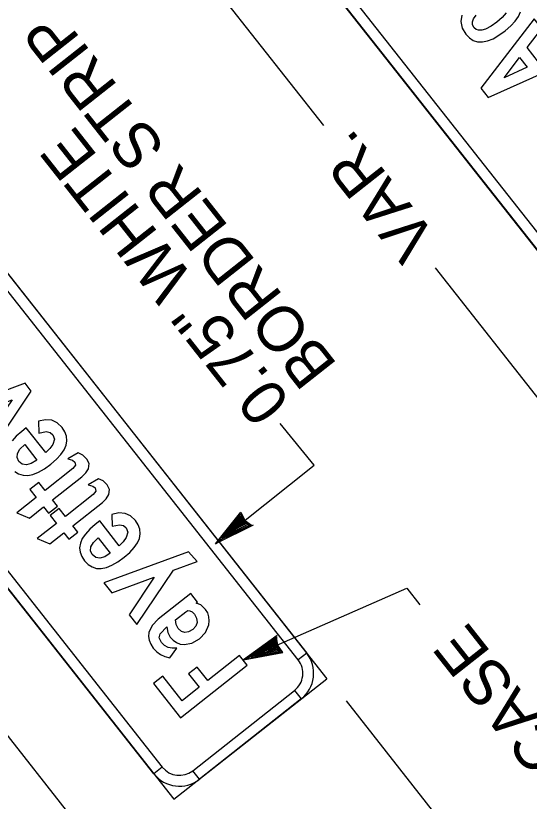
# Model space of a CAD drawing. Extents: x 672438 to 673763, y 1673171 to 1675010.
# Drawn here: x 673330.7 to 673378.2, y 1674719.6 to 1674792.2 of the extents above; entities that cross this region are included whole.
import ezdxf

# ---------------------------------------------------------------- set-up
doc = ezdxf.new("R2010")
doc.units = 0
for name, color, linetype in [('C-ANNO-SYMB', 7, 'Continuous'), ('Level 1', 7, 'Continuous'), ('V-SIGNAL-LOOP', 7, 'Continuous')]:
    doc.layers.add(name, color=color, linetype=linetype)

msp = doc.modelspace()

# ---------------------------------------------------------------- linework, layer by layer
at = {"layer": 'C-ANNO-SYMB'}
for p, q in [((673346.166, 1674812.112), (673390.741, 1674755.57)), ((673318.61, 1674782.748), (673359.471, 1674730.917)), ((673304.474, 1674771.604), (673345.335, 1674719.774)), ((673357.613, 1674733.273), (673356.828, 1674732.654)), ((673345.335, 1674719.774), (673359.471, 1674730.917)), ((673356.496, 1674729.845), (673357.115, 1674729.06)), ((673344.263, 1674722.749), (673343.478, 1674722.13)), ((673347.691, 1674721.631), (673347.072, 1674722.416))]:
    msp.add_line(p, q, dxfattribs=at)
for points in [[(673348.809, 1674810.375), (673389.669, 1674758.545), (673388.884, 1674757.926), (673348.023, 1674809.756), (673348.809, 1674810.375), (673348.809, 1674810.375)], [(673356.828, 1674732.654), (673319.682, 1674779.773), (673320.467, 1674780.392), (673357.613, 1674733.273), (673356.828, 1674732.654), (673356.828, 1674732.654)], [(673307.117, 1674769.867), (673344.263, 1674722.749), (673343.478, 1674722.13), (673306.332, 1674769.248), (673307.117, 1674769.867), (673307.117, 1674769.867)], [(673328.706, 1674752.423), (673332.141, 1674757.508), (673331.568, 1674758.235), (673325.816, 1674756.089), (673326.6, 1674755.207), (673330.366, 1674756.681), (673328.07, 1674753.342)], [(673335.529, 1674751.241), (673335.946, 1674751.111), (673336.182, 1674750.939), (673336.249, 1674750.652), (673336.003, 1674750.345), (673333.42, 1674748.308), (673332.841, 1674749.042), (673332.021, 1674748.396), (673332.6, 1674747.662), (673330.821, 1674746.26), (673331.984, 1674745.765), (673333.286, 1674746.792), (673333.745, 1674746.209), (673334.565, 1674746.855), (673334.106, 1674747.438), (673336.837, 1674749.591), (673337.204, 1674749.948), (673337.43, 1674750.331), (673337.486, 1674750.798), (673337.288, 1674751.227), (673336.908, 1674751.597), (673336.487, 1674751.786)], [(673337.412, 1674748.854), (673337.828, 1674748.723), (673338.064, 1674748.551), (673338.131, 1674748.265), (673337.885, 1674747.958), (673335.302, 1674745.921), (673334.723, 1674746.655), (673333.903, 1674746.009), (673334.482, 1674745.275), (673332.703, 1674743.873), (673333.866, 1674743.378), (673335.168, 1674744.404), (673335.628, 1674743.821), (673336.447, 1674744.468), (673335.988, 1674745.051), (673338.719, 1674747.204), (673339.087, 1674747.561), (673339.312, 1674747.943), (673339.368, 1674748.41), (673339.17, 1674748.839), (673338.79, 1674749.21), (673338.37, 1674749.399)], [(673347.499, 1674741.755), (673346.698, 1674742.646), (673338.865, 1674739.786), (673339.605, 1674738.847), (673343.521, 1674740.312), (673341.198, 1674736.827), (673341.903, 1674735.933), (673345.309, 1674740.944)], [(673352.117, 1674732.169), (673351.402, 1674733.077), (673348.468, 1674730.764), (673347.494, 1674732), (673346.682, 1674731.361), (673347.657, 1674730.124), (673346.086, 1674728.886), (673344.304, 1674731.147), (673343.458, 1674730.48), (673345.956, 1674727.311)], [(673347.072, 1674722.416), (673356.496, 1674729.845), (673357.115, 1674729.06), (673347.691, 1674721.631), (673347.072, 1674722.416), (673347.072, 1674722.416)]]:
    msp.add_lwpolyline(points, close=True, dxfattribs=at)
for points in [[(673371.959, 1674792.26), (673371.866, 1674791.664), (673371.991, 1674791.061), (673372.324, 1674790.488), (673372.655, 1674790.145), (673373.02, 1674789.916), (673373.422, 1674789.793), (673373.859, 1674789.779), (673374.335, 1674789.874), (673374.844, 1674790.076), (673375.39, 1674790.387), (673375.973, 1674790.806), (673376.495, 1674791.258), (673376.905, 1674791.701), (673377.207, 1674792.137), (673377.393, 1674792.565)], [(673376.067, 1674792.472), (673375.704, 1674792.032), (673375.208, 1674791.593), (673374.668, 1674791.219), (673374.148, 1674790.969), (673373.807, 1674790.867), (673373.514, 1674790.854), (673373.276, 1674790.927), (673373.086, 1674791.089), (673372.954, 1674791.346), (673372.941, 1674791.623), (673373.05, 1674791.924), (673373.274, 1674792.244)], [(673381.774, 1674787.943), (673381.069, 1674788.837), (673379.044, 1674787.917), (673377.996, 1674789.246), (673379.348, 1674791.02), (673378.638, 1674791.92), (673373.702, 1674785.509), (673374.388, 1674784.639), (673381.774, 1674787.943)], [(673377.996, 1674787.443), (673375.864, 1674786.468), (673377.29, 1674788.338), (673377.996, 1674787.443)], [(673330.613, 1674750.087), (673330.98, 1674749.853), (673331.385, 1674749.728), (673331.823, 1674749.715), (673332.303, 1674749.81), (673332.815, 1674750.014), (673333.363, 1674750.328), (673333.949, 1674750.75), (673334.468, 1674751.198), (673334.876, 1674751.64), (673335.174, 1674752.074), (673335.358, 1674752.5), (673335.436, 1674752.919), (673335.398, 1674753.334), (673335.251, 1674753.741), (673334.992, 1674754.14), (673334.547, 1674754.568), (673334.036, 1674754.806), (673333.46, 1674754.854), (673332.814, 1674754.71), (673332.851, 1674753.63), (673333.525, 1674753.758), (673333.881, 1674753.686), (673334.147, 1674753.473), (673334.284, 1674753.071), (673334.127, 1674752.57), (673333.861, 1674752.186), (673333.493, 1674751.819)], [(673333.493, 1674751.819), (673331.689, 1674754.106), (673331.264, 1674753.771), (673330.764, 1674753.335), (673330.367, 1674752.902)], [(673332.666, 1674751.127), (673332.149, 1674750.805), (673331.699, 1674750.677), (673331.318, 1674750.741), (673331.005, 1674750.997), (673330.837, 1674751.351), (673330.868, 1674751.731), (673331.104, 1674752.131), (673331.54, 1674752.556), (673332.666, 1674751.127)], [(673340.278, 1674743.212), (673338.474, 1674745.499), (673338.05, 1674745.164), (673337.549, 1674744.728), (673337.152, 1674744.295), (673336.867, 1674743.869), (673336.687, 1674743.449), (673336.621, 1674743.032), (673336.66, 1674742.621), (673336.811, 1674742.217), (673337.065, 1674741.82), (673337.398, 1674741.48), (673337.765, 1674741.246), (673338.17, 1674741.121), (673338.608, 1674741.108), (673339.088, 1674741.203), (673339.6, 1674741.407), (673340.149, 1674741.721), (673340.735, 1674742.143), (673341.253, 1674742.591), (673341.661, 1674743.033), (673341.96, 1674743.467), (673342.143, 1674743.893), (673342.221, 1674744.312), (673342.184, 1674744.727), (673342.037, 1674745.134), (673341.777, 1674745.533), (673341.332, 1674745.961), (673340.821, 1674746.199), (673340.245, 1674746.247), (673339.599, 1674746.103), (673339.636, 1674745.022), (673340.31, 1674745.151), (673340.666, 1674745.079), (673340.932, 1674744.866), (673341.069, 1674744.464), (673340.913, 1674743.963), (673340.646, 1674743.579), (673340.278, 1674743.212)], [(673339.451, 1674742.52), (673338.934, 1674742.198), (673338.484, 1674742.07), (673338.103, 1674742.134), (673337.791, 1674742.39), (673337.623, 1674742.744), (673337.654, 1674743.124), (673337.889, 1674743.524), (673338.325, 1674743.949), (673339.451, 1674742.52)], [(673347.531, 1674737.987), (673346.894, 1674738.795), (673343.894, 1674736.43), (673343.316, 1674735.836), (673343.019, 1674735.195), (673342.988, 1674734.831), (673343.043, 1674734.47), (673343.19, 1674734.108), (673343.425, 1674733.752), (673343.746, 1674733.411), (673344.106, 1674733.148), (673344.511, 1674732.961), (673344.953, 1674732.851), (673345.608, 1674733.729), (673345.179, 1674733.73), (673344.797, 1674733.818), (673344.474, 1674733.995), (673344.203, 1674734.256), (673343.985, 1674734.692), (673344.051, 1674735.078), (673344.667, 1674735.729), (673344.761, 1674735.185), (673344.976, 1674734.766), (673345.258, 1674734.471), (673345.566, 1674734.259), (673345.908, 1674734.125), (673346.277, 1674734.069), (673347.003, 1674734.192), (673347.709, 1674734.601), (673348.254, 1674735.187), (673348.552, 1674735.891), (673348.609, 1674736.281), (673348.576, 1674736.65), (673348.459, 1674736.995), (673348.254, 1674737.317), (673347.823, 1674737.739), (673347.407, 1674737.889), (673347.531, 1674737.987)], [(673345.477, 1674736.368), (673346.425, 1674737.115), (673346.619, 1674737.213), (673346.817, 1674737.207), (673347.022, 1674737.096), (673347.229, 1674736.879), (673347.44, 1674736.507), (673347.479, 1674736.131), (673347.357, 1674735.778), (673347.072, 1674735.47), (673346.694, 1674735.243), (673346.345, 1674735.179), (673346.025, 1674735.281), (673345.731, 1674735.549), (673345.537, 1674735.919), (673345.477, 1674736.368)]]:
    msp.add_lwpolyline(points, dxfattribs=at)
for centre, radius, start, end in [((673355.257, 1674731.416), 3, 308.25039, 38.2506), ((673355.257, 1674731.416), 2, 308.25039, 38.2506), ((673345.834, 1674723.987), 2, 218.25075, 308.25039), ((673345.834, 1674723.987), 3, 218.25075, 308.25039)]:
    msp.add_arc(centre, radius, start, end, dxfattribs=at)
at = {"layer": 'Level 1'}
for p, q in [((673359.186, 1674782.058), (673343.23, 1674802.298)), ((673384.125, 1674750.354), (673369.51, 1674768.893)), ((673349.19, 1674743.399), (673351.51, 1674746.31)), ((673351.51, 1674746.31), (673351.902, 1674745.55)), ((673349.408, 1674743.636), (673351.491, 1674746.161)), ((673349.759, 1674743.911), (673351.489, 1674745.993)), ((673349.977, 1674744.011), (673351.532, 1674745.727)), ((673350.049, 1674744.135), (673351.49, 1674745.861)), ((673350.483, 1674744.474), (673351.476, 1674745.583)), ((673351.535, 1674745.596), (673351.029, 1674744.837)), ((673351.476, 1674745.583), (673351.83, 1674745.261)), ((673351.489, 1674745.993), (673351.627, 1674745.733)), ((673351.49, 1674745.861), (673352.171, 1674745.163)), ((673351.491, 1674746.161), (673351.833, 1674745.596)), ((673351.532, 1674745.727), (673351.992, 1674745.222)), ((673351.911, 1674745.325), (673351.535, 1674745.596)), ((673351.627, 1674745.733), (673352.171, 1674745.163)), ((673351.833, 1674745.596), (673352.503, 1674745.123)), ((673352.65, 1674745.105), (673349.19, 1674743.399)), ((673352.293, 1674745.091), (673349.45, 1674743.667)), ((673352.458, 1674745.053), (673349.61, 1674743.759)), ((673352.171, 1674745.163), (673349.977, 1674744.011)), ((673352.171, 1674745.163), (673350.049, 1674744.135)), ((673351.992, 1674745.222), (673350.483, 1674744.474)), ((673350.87, 1674744.744), (673351.441, 1674745.456)), ((673351.83, 1674745.261), (673350.87, 1674744.744)), ((673351.205, 1674745.039), (673351.471, 1674745.379)), ((673351.722, 1674745.31), (673351.205, 1674745.039)), ((673351.441, 1674745.456), (673351.722, 1674745.31)), ((673351.471, 1674745.379), (673351.553, 1674745.314)), ((673351.553, 1674745.314), (673351.911, 1674745.325)), ((673351.902, 1674745.55), (673352.144, 1674745.241)), ((673352.144, 1674745.241), (673352.458, 1674745.053)), ((673352.503, 1674745.123), (673352.284, 1674745.186)), ((673352.284, 1674745.186), (673352.293, 1674745.091)), ((673351.029, 1674744.837), (673350.776, 1674744.737)), ((673354.877, 1674734.922), (673351.757, 1674732.653)), ((673354.741, 1674734.777), (673352.271, 1674732.857)), ((673354.761, 1674734.411), (673354.741, 1674734.777)), ((673354.825, 1674734.784), (673354.779, 1674734.56)), ((673354.931, 1674733.97), (673354.825, 1674734.784)), ((673354.698, 1674734.612), (673352.115, 1674732.758)), ((673354.705, 1674734.471), (673352.665, 1674733.065)), ((673354.705, 1674734.471), (673352.808, 1674733.071)), ((673354.674, 1674734.285), (673353.31, 1674733.297)), ((673354.633, 1674734.123), (673353.729, 1674733.514)), ((673354.627, 1674734.005), (673354.146, 1674733.674)), ((673354.551, 1674733.854), (673354.727, 1674734.165)), ((673354.625, 1674733.688), (673354.627, 1674734.005)), ((673354.754, 1674733.661), (673354.633, 1674734.123)), ((673354.907, 1674733.642), (673354.674, 1674734.285)), ((673354.779, 1674734.56), (673354.698, 1674734.612)), ((673354.956, 1674733.724), (673354.705, 1674734.471)), ((673355.006, 1674733.544), (673354.705, 1674734.471)), ((673354.727, 1674734.165), (673354.792, 1674733.706)), ((673354.923, 1674734.053), (673354.761, 1674734.411)), ((673355.412, 1674733.352), (673354.923, 1674734.053)), ((673355.272, 1674733.405), (673354.931, 1674733.97)), ((673351.757, 1674732.653), (673355.412, 1674733.352)), ((673352.067, 1674732.735), (673355.272, 1674733.405)), ((673352.238, 1674732.928), (673352.986, 1674733.437)), ((673352.475, 1674732.918), (673355.122, 1674733.481)), ((673352.986, 1674733.437), (673352.475, 1674732.918)), ((673352.665, 1674733.065), (673354.907, 1674733.642)), ((673352.808, 1674733.071), (673355.006, 1674733.544)), ((673353.203, 1674733.277), (673353.589, 1674733.565)), ((673353.679, 1674733.434), (673353.203, 1674733.277)), ((673353.31, 1674733.297), (673354.754, 1674733.661)), ((673353.886, 1674733.612), (673353.679, 1674733.434)), ((673353.729, 1674733.514), (673354.625, 1674733.688)), ((673354.792, 1674733.706), (673353.886, 1674733.612)), ((673354.146, 1674733.674), (673354.571, 1674733.751)), ((673354.571, 1674733.751), (673354.551, 1674733.854)), ((673355.122, 1674733.481), (673354.956, 1674733.724)), ((673338.711, 1674714.552), (673324.096, 1674733.09)), ((673352.271, 1674732.857), (673352.067, 1674732.735)), ((673352.115, 1674732.758), (673352.238, 1674732.928)), ((673361.25, 1674728.874), (673370.079, 1674717.675))]:
    msp.add_line(p, q, dxfattribs=at)
for points in [[(673349.19, 1674743.399), (673358.303, 1674750.66), (673355.165, 1674754.516)], [(673351.757, 1674732.653), (673366.865, 1674739.29), (673368.088, 1674737.739)]]:
    msp.add_lwpolyline(points, dxfattribs=at)
at = {"layer": 'V-SIGNAL-LOOP'}
msp.add_lwpolyline([(673363.264, 1674738.11), (673363.264, 1674738.11), (673363.264, 1674738.11)], dxfattribs=at)

# ---------------------------------------------------------------- texts
at = {"layer": 'Level 1'}
for s, p in [('BORDER STRIP', (673360.529, 1674759.913)), ('0.75" WHITE ', (673356.235, 1674756.528)), ('VAR.', (673369.771, 1674771.612)), ('8" UPPERCASE', (673398.009, 1674703.791))]:
    msp.add_text(s, height=4.2, rotation=128.25054, dxfattribs=at).set_placement(p)

doc.saveas('drawing.dxf')
